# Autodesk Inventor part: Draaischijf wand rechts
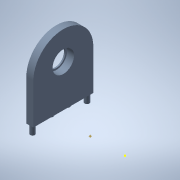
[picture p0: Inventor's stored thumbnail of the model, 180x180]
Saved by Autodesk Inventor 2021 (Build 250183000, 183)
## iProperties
Manager: Pierloot J.
Company: Emmaüs Bovenbouw Aalter
Created: 2015-08
Part Number: Draaischijf wand rechts
Material: S235
Catalog Web Link: http://emmausbovenbouw.op-weg.be/
Vendor: Emmaüsinstituut Bovenbouw Aalter
Document SubType Name: Modeling
Designer: Pierlootj
Engineer: Pierloot J.
Manufacturer: Standard
Standards Organization: Custom
Density: 7.86 g/cm^3
Appearance: Light Steel Blue
Title: Algemene titel
Subject: Specifieke titel
Author: Pierlootj
Keywords: Ruwe Ø xxxxx
Comments: Opmerking
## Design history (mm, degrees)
sketch "Sketch14"
  geometry: L1 (0, 0)-(-24.5, 0); L2 (-24.5, 0)-(24.5, 0); L3 (-24.5, 0)-(-24.5, -21.354); L4 (-24.5, 21.354)-(-19.5, 21.354); L5 (-19.5, 21.354)-(-19.5, -21.354); L6 (-19.5, -21.354)-(-24.5, -21.354); L7 (-24.5, -21.354)-(-24.5, 21.354); L8 (0, 27.067)-(0, -27.009); L9 (19.5, -21.354)-(24.5, -21.354); L10 (19.5, 21.354)-(19.5, -21.354); L11 (24.5, -21.354)-(24.5, 21.354); L12 (24.5, 21.354)-(19.5, 21.354); A1 r 32.5 centre (0, 0) between (-24.5, -21.354) and (-24.5, 21.354)
  constraints: 24 end point, 4 symmetric about line, 2 horizontal, 2 parallel, 2 point on circle, 2 vertical, 1 centre point, 1 coincident, 1 perpendicular, 1 point on line
  dimensions: "d105" = 24.5 distance of L1.start L1.end; "d106" = 49 distance of L1.end L2.end; "d107" = 65 diameter of A1; "d108" = 5 distance of L5.end L6.end
extrude "Extrusion12" new body sketch "Sketch14" distance "d109" = 6; taper "d110" = 0 deg
sketch "Sketch15"
  geometry: L1 (0, 0)-(-24.5, 0); L2 (-24.5, 0)-(24.5, 0); L3 (-24.5, -21.354)-(-24.5, 21.354); L4 (0, 27.067)-(0, -27.009); L5 (19.5, -21.354)-(24.5, -21.354); L6 (19.5, 21.354)-(19.5, -21.354); L7 (24.5, -21.354)-(24.5, 21.354); L8 (24.5, 21.354)-(19.5, 21.354); L9 (-24.5, -21.354)-(-19.5, -21.354); L10 (-19.5, -21.354)-(-19.5, 21.354); L11 (-19.5, 21.354)-(-24.5, 21.354); L12 (-24.5, 21.354)-(-24.5, -21.354); 1 further point
  constraints: 24 end point, 2 horizontal, 2 parallel, 2 symmetric about line, 1 perpendicular, 1 point on line, 1 vertical
  dimensions: "d111" = 24.5 distance of L1.start L1.end; "d112" = 49 distance of L1.end L2.end; "d131" = 5 distance of L11.end L10.end
extrude "Extrusion13" join sketch "Sketch15" distance "d115" = 50; taper "d116" = 0 deg
fillet "Fillet5" dims "d117" = 21.3
sketch "Sketch17"
  geometry: L1 (0, 42.708)-(0, 0) reference; L2 (0, 21.354)-(-30, 21.354); L3 (-30, 21.354)-(-13.35, 21.354); L4 (-13.35, 21.354)-(-13.35, 27.509); L5 (-13.35, 27.509)-(-36.15, 27.509); L6 (-36.15, 27.509)-(-36.15, 15.209); L7 (-36.15, 15.209)-(-13.35, 15.209); L8 (-13.35, 15.209)-(-13.35, 27.509); 2 further points
  constraints: 14 end point, 2 horizontal, 2 parallel, 2 perpendicular, 1 midpoint, 1 point on line
  dimensions: "d122" = 30 distance of L2.start L2.end; "d190" = 16.65 distance of L2.end L3.end; "d191" = 22.8 distance of L7.end L6.end; "d192" = 12.3 distance of L6.end L5.end
sketch "Sketch19"
  geometry: L1 (0, 0)-(0, 42.708) reference; L2 (0, 21.354)-(30, 21.354); C1 r 7.65 at (30, 21.354); 1 further point
  constraints: 2 end point, 1 centre point, 1 coincident, 1 horizontal, 1 midpoint
  dimensions: "d132" = 30 distance of L2.start L2.end; "d184" = 15.3 diameter of C1
fillet "Fillet6" dims "d136" = 21.3
sketch "Sketch20"
  geometry: C1 r 13 at (30, 21.354) reference; C2 r 6.5 at (30, 21.354); C3 r 7.75 at (30, 21.354); 1 further point
  constraints: 2 centre point, 2 coincident
  dimensions: "d137" = 13 diameter of C2; "d138" = 15.5 diameter of C3
extrude "Extrusion18" join sketch "Sketch20" distance "d139" = 1; taper "d140" = 0 deg
sketch "Sketch21"
  geometry: C1 r 2.5 at (0, 0) reference; C2 r 26.15 at (0, 0); C3 r 17.35 at (0, 0); 1 further point
  constraints: 2 centre point, 2 coincident
  dimensions: "d144" = 52.3 diameter of C2; "d145" = 34.7 diameter of C3
extrude "Extrusion19" cut sketch "Sketch21" distance "d146" = 4.3; taper "d147" = 0 deg
sketch "Sketch22"
  geometry: 1 further point
sketch "Sketch23"
  geometry: L1 (-35.75, 27.504)-(-35.75, 15.204) reference; L2 (-35.75, 21.354)-(-38.25, 21.354); L3 (-13.25, 27.504)-(-13.25, 15.204) reference; L4 (-13.25, 21.354)-(-11.25, 21.354); C1 r 0.5 at (-38.25, 21.354); C2 r 0.5 at (-11.25, 21.354); 1 further point
  constraints: 4 end point, 2 centre point, 2 coincident, 2 horizontal, 2 midpoint
  dimensions: "d150" = 2.5 distance of L2.start L2.end; "d151" = 1 diameter of C1; "d152" = 2 distance of L4.start L4.end; "d153" = 1 diameter of C2
extrude "Extrusion21" cut sketch "Sketch23" stored distance "d154" = 4.3; taper "d155" = 0 deg
extrude "Extrusion23" cut sketch "Sketch19" stored distance "d185" = 10; taper "d186" = 0 deg
chamfer "Chamfer2" distance "d187" = 1; stored, may be unused: second distance "d188" = 2, angle "d189" = 45 deg
extrude "Extrusion24" cut sketch "Sketch17" stored distance "d193" = 10; taper "d194" = 0 deg
sketch "Sketch25"
  geometry: L1 (2.197, 15.216)-(2.899, 1.91); L2 (-2.197, 15.216)-(-2.894, 2.01); L3 (2.899, 1.91)-(3, 0); L4 (-2.894, 2.01)-(-3, 0); L5 (-13.698, 0)-(13.244, 0); L6 (2.197, -15.216)-(2.899, -1.91); L7 (-2.197, -15.216)-(-2.894, -2.01); L8 (-2.894, -2.01)-(-3, 0); L9 (2.899, -1.91)-(3, 0); L10 (7.35, 1.1)-(3.327, 1.1); L11 (-3.454, 1.1)-(-7.35, 1.1); L12 (7.35, -1.1)-(3.207, -1.1); L13 (-3.263, -1.238)-(-7.387, -1.099); L14 (-3.876, 2.377)-(-3.196, 15.269); L15 (3.196, 15.269)-(3.884, 2.229); L16 (3.959, 2.1)-(7.35, 2.1); L17 (7.35, -2.1)-(3.918, -2.1); L18 (3.887, -2.168)-(3.196, -15.269); L19 (-3.196, -15.269)-(-3.879, -2.313); L20 (-3.932, -2.216)-(-7.421, -2.099); L21 (-7.35, 2.1)-(-4.061, 2.1); A1 r 2.2 centre (0, 15.1) between (2.197, 15.216) and (-2.197, 15.216); A2 r 2.2 centre (0, -15.1) between (-2.197, -15.216) and (2.197, -15.216); A3 r 1.1 centre (7.35, 0) between (7.35, -1.1) and (7.35, 1.1); A4 r 1.1 centre (-7.35, 0) between (-7.35, 1.1) and (-7.387, -1.099); A5 r 3.537 centre (-0.229, -0.259) between (2.899, -1.91) and (3.207, -1.1); A6 r 3.806 centre (-0.229, -0.259) between (3.327, 1.1) and (2.899, 1.91); A7 r 3.5 centre (-0.229, -0.259) between (-2.894, 2.01) and (-3.454, 1.1); A8 r 3.189 centre (-0.229, -0.259) between (-3.263, -1.238) and (-2.894, -2.01); A9 r 4.806 centre (-0.229, -0.259) between (3.959, 2.1) and (3.884, 2.229); A10 r 2.1 centre (7.35, 0) between (7.35, -2.1) and (7.35, 2.1); A11 r 4.537 centre (-0.229, -0.259) between (3.887, -2.168) and (3.918, -2.1); A12 r 4.189 centre (-0.229, -0.259) between (-3.932, -2.216) and (-3.879, -2.313); A13 r 2.1 centre (-7.35, 0) between (-7.35, 2.1) and (-7.421, -2.099); A14 r 4.5 centre (-0.229, -0.259) between (-3.876, 2.377) and (-4.061, 2.1); A15 r 17.35 centre (0, 0) between (2.433, 17.179) and (-2.433, 17.179) reference; A16 r 17.35 centre (0, 0) between (2.433, 17.179) and (-2.433, 17.179); A17 r 17.35 centre (0, 0) between (-2.433, -17.179) and (2.433, -17.179); A18 r 3.2 centre (0, 15.1) between (3.196, 15.269) and (2.433, 17.179); A19 r 3.2 centre (0, 15.1) between (-2.433, 17.179) and (-3.196, 15.269); A20 r 3.2 centre (0, -15.1) between (-3.196, -15.269) and (-2.433, -17.179); A21 r 3.2 centre (0, -15.1) between (2.433, -17.179) and (3.196, -15.269); 3 further points
  constraints: 44 point on circle, 42 end point, 20 centre point, 6 tangent, 5 symmetric about line, 3 point on line, 2 coincident, 2 horizontal alignment, 2 parallel, 1 horizontal, 1 vertical alignment, 12 other
  dimensions: "d197" = 3 distance of L3.end point (0, 0); "d198" = 3 distance of L4.end point (0, 0); "d199" = 15.1 distance of A1.centre point (0, 0); "d200" = 2.2 radius of A1; "d201" = 2.2 diameter of A3; "d202" = 2.2 diameter of A4; "d203" = 14.7 distance of A4.centre A3.centre; "d204" = 7.35 distance of point (0, 0) A3.centre (derived); "d205" = 1 distance between parallel lines of L2 L14
extrude "Extrusion26" join sketch "Sketch25" distance "d206" = 2.6; taper "d207" = 0 deg
chamfer "Chamfer3" distance "d208" = 1; stored, may be unused: second distance "d209" = 2, angle "d210" = 45 deg
sketch "Sketch26"
  geometry: L1 (-4.67, 16.71)-(-4.498, 15.719); L2 (4.609, 15.687)-(5.257, 16.534); L3 (-13.838, 0)-(14.49, 0); L4 (4.609, -15.687)-(5.257, -16.534); L5 (-4.67, -16.71)-(-4.498, -15.719); A1 r 17.35 centre (0, 0) between (3.779, -16.934) and (3.779, 16.934) reference; A2 r 17.35 centre (0, 0) between (-3.779, 16.934) and (-3.779, -16.934) reference; A3 r 17.35 centre (0, 0) between (5.257, 16.534) and (-4.67, 16.71); A4 r 16.35 centre (0, 0) between (4.609, 15.687) and (-4.498, 15.719); A5 r 17.35 centre (0, 0) between (-4.67, -16.71) and (5.257, -16.534); A6 r 16.35 centre (0, 0) between (-4.498, -15.719) and (4.609, -15.687); 7 further points
  constraints: 10 end point, 10 point on circle, 4 centre point, 4 symmetric about line, 2 coincident, 1 horizontal, 2 other
  dimensions: "d211" = 16.35 radius of A4
extrude "Extrusion27" cut sketch "Sketch26" distance "d212" = 2.6; taper "d213" = 0 deg
sketch "Sketch29"
  geometry: L1 (24.5, 21.354)-(24.5, -21.354) reference; L2 (24.5, 0)-(26, 0); L3 (26, 0)-(26, 4.25); L4 (26, 4.25)-(29.5, 4.25); L5 (29.5, 4.25)-(29.5, -4.25); L6 (29.5, -4.25)-(26, -4.25); L7 (26, -4.25)-(26, 4.25); 2 further points
  constraints: 12 end point, 2 horizontal, 2 parallel, 2 perpendicular, 1 midpoint
  dimensions: "d226" = 1.5 distance of L2.start L2.end; "d227" = 4.25 distance of L2.end L3.end; "d228" = 3.5 distance of L5.end L6.end; "d229" = 8.5 distance of L4.end L5.end
extrude "Extrusion30" cut sketch "Sketch29" extent not by distance; stored distance "d230" = 0; taper "d231" = 0 deg
sketch "Sketch30"
  geometry: C1 r 64.799 at (0, 0); 1 further point
  constraints: 1 centre point, 1 coincident
extrude "Extrusion31" cut sketch "Sketch30" distance "d232" = 8.6; taper "d233" = 0 deg
sketch "Sketch32"
  geometry: L1 (-24.5, -21.354)-(-19.5, -17.423); L2 (-19.5, -17.423)-(-22, -19.389); L3 (0, 0)-(-22.867, 0); L4 (0, -23.308)-(0, 14.95); C1 r 1.65 at (-22, -19.389); C2 r 1.65 at (-22, 19.389); C3 r 1.65 at (22, -19.389); C4 r 1.65 at (22, 19.389); 1 further point
  constraints: 8 end point, 4 centre point, 3 symmetric about line, 1 coincident, 1 horizontal, 1 midpoint, 1 vertical, 3 other
  dimensions: "d236" = 3.3 diameter of C1
extrude "Extrusion33" join sketch "Sketch32" distance "d237" = 6; taper "d238" = 0 deg
sketch "Sketch33"
  geometry: L1 (19.5, -21.354)-(24.5, -21.354) reference; L2 (24.5, -21.354)-(24.5, 0); L3 (19.5, 21.354)-(24.5, 21.354) reference; L4 (24.5, 0)-(22, 0); L5 (19.5, -0.054)-(19.5, 0.054) reference; L6 (22, 0)-(22, -6); L7 (22, -6)-(22, 6); L8 (0, 0)-(0, -14.735); C1 r 1.25 at (22, -6); C2 r 1.25 at (22, 6); C3 r 1.25 at (-22, -6); C4 r 1.25 at (-22, 6)
  constraints: 10 end point, 4 centre point, 2 coincident, 2 perpendicular, 2 symmetric about line, 2 vertical, 1 point on line, 2 other
  dimensions: "d239" = 2.5 distance of L2.end L4.end; "d240" = 6 distance of L4.end L6.end; "d241" = 12 distance of L6.end L7.end; "d242" = 2.5 diameter of C1; "d243" = 2.5 diameter of C2
extrude "Extrusion34" join sketch "Sketch33" distance "d244" = 1.7; taper "d245" = 0 deg
sketch "Sketch34"
  geometry: C1 r 56.583 at (-27.874, 19.199); 1 further point
  constraints: 1 centre point
extrude "Extrusion35" cut sketch "Sketch34" distance "d246" = 10; taper "d247" = 0 deg
body "Solid6"
